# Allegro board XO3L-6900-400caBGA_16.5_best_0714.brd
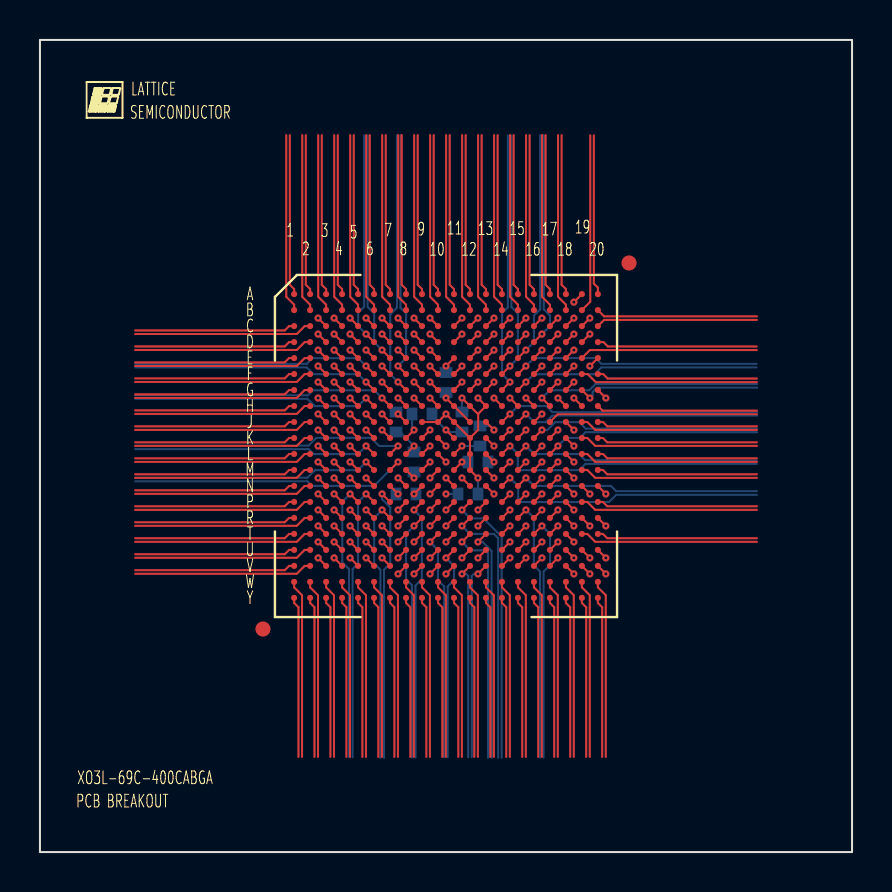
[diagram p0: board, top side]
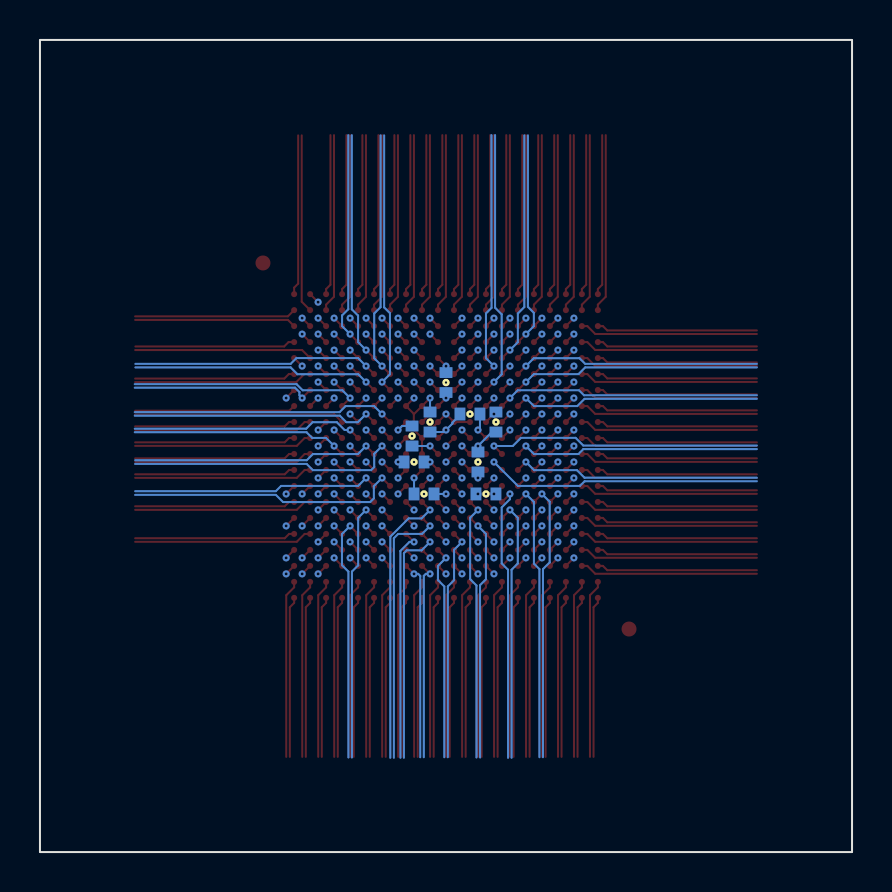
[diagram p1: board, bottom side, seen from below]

Outline 40.64 x 40.64 mm; copper layers: TOP, L2_GND, L3_SIGNAL, L4_SIGNAL, L5_PWR, BOTTOM. Coordinates in mm from the lower left corner of the outline.
Outline path: rectangle 0,0 40.64,40.64

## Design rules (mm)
net group CDPB4: nets PB4C PB4D
net group CDPB6: nets PB6C PB6D
net group CDPB7: nets PB7C PB7D
net group CDPB9: nets PB9C PB9D
net group CDPB10: nets PB10C PB10D
net group CDPB12: nets PB12C PB12D
net group CDPB13: nets PB13C PB13D
net group CDPB15: nets PB15C PB15D
net group CDPB16: nets PB16C PB16D
net group CDPB18: nets PB18C PB18D
net group CDPB21: nets PB21C PB21D
net group CDPB23: nets PB23C PB23D
net group CDPB26: nets PB26C PB26D
net group CDPB28: nets PB28C PB28D
net group CDPB29: nets PB29C PB29D
net group CDPB31: nets PB31C PB31D
net group CDPB32: nets PB32C PB32D
net group CDPB34: nets PB34C PB34D
net group CDPB35: nets PB35C PB35D
net group CDPB37: nets PB37C PB37D
net group CDPB38: nets PB38C PB38D
net group CDPL2: nets PL2C PL2D
net group CDPL3: nets PL3C PL3D
net group CDPL4: nets PL4C PL4D
net group CDPL5: nets PL5C PL5D
net group CDPL6: nets PL6C PL6D
net group CDPL7: nets PL7C PL7D
net group CDPL8: nets PL8C PL8D
net group CDPL9: nets PL9C PL9D
net group CDPL10: nets PL10C PL10D
net group CDPL11: nets PL11C PL11D
net group CDPL12: nets PL12C PL12D
net group CDPL14: nets PL14C PL14D
net group CDPL15: nets PL15C PL15D
net group CDPL16: nets PL16C PL16D
net group CDPL17: nets PL17C PL17D
net group CDPL18: nets PL18C PL18D
net group CDPL19: nets PL19C PL19D
net group CDPL20: nets PL20C PL20D
net group CDPL21: nets PL21C PL21D
net group CDPL22: nets PL22C PL22D
net group CDPL23: nets PL23C PL23D
net group CDPL24: nets PL24C PL24D
net group CDPL25: nets PL25C PL25D
net group CDPL26: nets PL26C PL26D
net group CDPL29: nets PL29C PL29D
net group CDPL32: nets PL32C PL32D
net group CDPL35: nets PL35C PL35D
net group CDPL38: nets PL38C PL38D
net group CDPL41: nets PL41C PL41D
net group CDPL44: nets PL44C PL44D
net group CDPL47: nets PL47C PL47D
net group CDPL50: nets PL50C PL50D
net group CDPL53: nets PL53C PL53D
net group CDPL56: nets PL56C PL56D
net group CDPL59: nets PL59C PL59D
net group CDPL62: nets PL62C PL62D
net group CDPL65: nets PL65C PL65D
net group CDPL68: nets PL68C PL68D
net group CDPL71: nets PL71C PL71D
net group CDPL74: nets PL74C PL74D
net group CDPL77: nets PL77C PL77D
net group CDPL80: nets PL80C PL80D
net group CDPL83: nets PL83C PL83D
net group CDPL86: nets PL86C PL86D
net group CDPL89: nets PL89C PL89D
net group CDPL92: nets PL92C PL92D
net group CDPR2: nets PR2C PR2D
net group CDPR3: nets PR3C PR3D
net group CDPR4: nets PR4C PR4D
net group CDPR5: nets PR5C PR5D
net group CDPR6: nets PR6C PR6D
net group CDPR7: nets PR7C PR7D
net group CDPR8: nets PR8C PR8D
net group CDPR9: nets PR9C PR9D
net group CDPR10: nets PR10C PR10D
net group CDPR11: nets PR11C PR11D
net group CDPR12: nets PR12C PR12D
net group CDPR14: nets PR14C PR14D
net group CDPR15: nets PR15C PR15D
net group CDPR16: nets PR16C PR16D
net group CDPR17: nets PR17C PR17D
net group CDPR18: nets PR18C PR18D
net group CDPR19: nets PR19C PR19D
net group CDPR20: nets PR20C PR20D
net group CDPR21: nets PR21C PR21D
net group CDPR22: nets PR22C PR22D
net group CDPR23: nets PR23C PR23D
net group CDPR24: nets PR24C PR24D
net group CDPR25: nets PR25C PR25D
net group CDPR26: nets PR26C PR26D
net group CDPR29: nets PR29C PR29D
net group CDPR32: nets PR32C PR32D
net group CDPR35: nets PR35C PR35D
net group CDPR38: nets PR38C PR38D
net group CDPR41: nets PR41C PR41D
net group CDPR44: nets PR44C PR44D
net group CDPR47: nets PR47C PR47D
net group CDPR50: nets PR50C PR50D
net group CDPR53: nets PR53C PR53D
net group CDPR56: nets PR56C PR56D
net group CDPR59: nets PR59C PR59D
net group CDPR62: nets PR62C PR62D
net group CDPR65: nets PR65C PR65D
net group CDPR68: nets PR68C PR68D
net group CDPR71: nets PR71C PR71D
net group CDPR74: nets PR74C PR74D
net group CDPR77: nets PR77C PR77D
net group CDPR80: nets PR80C PR80D
net group CDPR83: nets PR83C PR83D
net group CDPR86: nets PR86C PR86D
net group CDPR89: nets PR89C PR89D
net group CDPR92: nets PR92C PR92D
net group CDPT9: nets PT9C PT9D
net group CDPT10: nets PT10C PT10D
net group CDPT11: nets PT11C PT11D
net group CDPT12: nets PT12C PT12D
net group CDPT13: nets PT13C PT13D
net group CDPT14: nets PT14C PT14D
net group CDPT15: nets PT15C PT15D
net group CDPT16: nets PT16C PT16D
net group CDPT17: nets PT17C PT17D
net group CDPT18: nets PT18C PT18D
net group CDPT21: nets PT21C PT21D
net group CDPT22: nets PT22C PT22D
net group CDPT25: nets PT25C PT25D
net group CDPT26: nets PT26C PT26D
net group CDPT27: nets PT27C PT27D
net group CDPT28: nets PT28C PT28D
net group CDPT32: nets PT32C PT32D
net group CDPT33: nets PT33C PT33D
net group CDPT34: nets PT34C PT34D
net group CDPT35: nets PT35C PT35D
net group CDPT36: nets PT36C PT36D
net group PB4: nets PB4A PB4B
net group PB6: nets PB6A PB6B
net group PB7: nets PB7A PB7B
net group PB9: nets PB9A PB9B
net group PB10: nets PB10A PB10B
net group PB12: nets PB12A PB12B
net group PB13: nets PB13A PB13B
net group PB15: nets PB15A PB15B
net group PB16: nets PB16A PB16B
net group PB18: nets PB18A PB18B
net group PB21: nets PB21A PB21B
net group PB23: nets PB23A PB23B
net group PB26: nets PB26A PB26B
net group PB28: nets PB28A PB28B
net group PB29: nets PB29A PB29B
net group PB31: nets PB31A PB31B
net group PB32: nets PB32A PB32B
net group PB34: nets PB34A PB34B
net group PB35: nets PB35A PB35B
net group PB37: nets PB37A PB37B
net group PB38: nets PB38A PB38B
net group PB98: nets PB98A PB98B
net group PL2: nets PL2A PL2B
net group PL3: nets PL3A PL3B
net group PL4: nets PL4A PL4B
net group PL5: nets PL5A PL5B
net group PL6: nets PL6A PL6B
net group PL7: nets PL7A PL7B
net group PL8: nets PL8A PL8B
net group PL9: nets PL9A PL9B
net group PL10: nets PL10A PL10B
net group PL11: nets PL11A PL11B
net group PL12: nets PL12A PL12B
net group PL14: nets PL14A PL14B
net group PL15: nets PL15A PL15B
net group PL16: nets PL16A PL16B
net group PL17: nets PL17A PL17B
net group PL18: nets PL18A PL18B
net group PL19: nets PL19A PL19B
net group PL20: nets PL20A PL20B
net group PL21: nets PL21A PL21B
net group PL22: nets PL22A PL22B
net group PL23: nets PL23A PL23B
net group PL24: nets PL24A PL24B
net group PL25: nets PL25A PL25B
net group PL29: nets PL29A PL29B
net group PL32: nets PL32A PL32B
net group PL35: nets PL35A PL35B
net group PL38: nets PL38A PL38B
net group PL41: nets PL41A PL41B
net group PL44: nets PL44A PL44B
net group PL47: nets PL47A PL47B
net group PL50: nets PL50A PL50B
net group PL53: nets PL53A PL53B
net group PL56: nets PL56A PL56B
net group PL59: nets PL59A PL59B
net group PL62: nets PL62A PL62B
net group PL65: nets PL65A PL65B
net group PL68: nets PL68A PL68B
net group PL71: nets PL71A PL71B
net group PL74: nets PL74A PL74B
net group PL77: nets PL77A PL77B
net group PL80: nets PL80A PL80B
net group PL83: nets PL83A PL83B
net group PL86: nets PL86A PL86B
net group PL89: nets PL89A PL89B
net group PL92: nets PL92A PL92B
net group PR2: nets PR2A PR2B
net group PR3: nets PR3A PR3B
net group PR4: nets PR4A PR4B
net group PR5: nets PR5A PR5B
net group PR6: nets PR6A PR6B
net group PR7: nets PR7A PR7B
net group PR8: nets PR8A PR8B
net group PR9: nets PR9A PR9B
net group PR10: nets PR10A PR10B
net group PR11: nets PR11A PR11B
net group PR12: nets PR12A PR12B
net group PR14: nets PR14A PR14B
net group PR15: nets PR15A PR15B
net group PR16: nets PR16A PR16B
net group PR17: nets PR17A PR17B
net group PR18: nets PR18A PR18B
net group PR19: nets PR19A PR19B
net group PR20: nets PR20A PR20B
net group PR21: nets PR21A PR21B
net group PR22: nets PR22A PR22B
net group PR23: nets PR23A PR23B
net group PR24: nets PR24A PR24B
net group PR25: nets PR25A PR25B
net group PR26: nets PR26A PR26B
net group PR29: nets PR29A PR29B
net group PR32: nets PR32A PR32B
net group PR35: nets PR35A PR35B
net group PR38: nets PR38A PR38B
net group PR41: nets PR41A PR41B
net group PR44: nets PR44A PR44B
net group PR47: nets PR47A PR47B
net group PR50: nets PR50A PR50B
net group PR53: nets PR53A PR53B
net group PR56: nets PR56A PR56B
net group PR59: nets PR59A PR59B
net group PR62: nets PR62A PR62B
net group PR65: nets PR65A PR65B
net group PR68: nets PR68A PR68B
net group PR71: nets PR71A PR71B
net group PR74: nets PR74A PR74B
net group PR77: nets PR77A PR77B
net group PR80: nets PR80A PR80B
net group PR83: nets PR83A PR83B
net group PR86: nets PR86A PR86B
net group PR89: nets PR89A PR89B
net group PR92: nets PR92A PR92B
net group PT4: nets PT4A PT4B
net group PT6: nets PT6A PT6B
net group PT9: nets PT9A PT9B
net group PT10: nets PT10A PT10B
net group PT11: nets PT11A PT11B
net group PT12: nets PT12A PT12B
net group PT13: nets PT13A PT13B
net group PT14: nets PT14A PT14B
net group PT15: nets PT15A PT15B
net group PT16: nets PT16A PT16B
net group PT17: nets PT17A PT17B
net group PT18: nets PT18A PT18B
net group PT20: nets PT20A PT20B
net group PT21: nets PT21A PT21B
net group PT22: nets PT22A PT22B
net group PT24: nets PT24A PT24B
net group PT25: nets PT25A PT25B
net group PT26: nets PT26A PT26B
net group PT27: nets PT27A PT27B
net group PT28: nets PT28A PT28B
net group PT29: nets PT29A PT29B
net group PT31: nets PT31A PT31B
net group PT32: nets PT32A PT32B
net group PT33: nets PT33A PT33B
net group PT34: nets PT34A PT34B
net group PT35: nets PT35A PT35B
net group PT36: nets PT36A PT36B
net group PT38: nets PT38A PT38B
net group PT40: nets PT40A PT40B
net group PT42: nets PT42A PT42B
net group PT44: nets PT44A PT44B
net group PT45: nets PT45A PT45B
net group PT47: nets PT47A PT47B
net group PT49: nets PT49A PT49B
net group PT51: nets PT51A PT51B
net group PT54: nets PT54A PT54B
net group PT56: nets PT56A PT56B
net group PT58: nets PT58A PT58B
net group PT60: nets PT60A PT60B
net group PT63: nets PT63A PT63B
net group PT65: nets PT65A PT65B
net group PT69: nets PT69A PT69B
net group PT71: nets PT71A PT71B
net group PT74: nets PT74A PT74B
net group PT76: nets PT76A PT76B
net group PT101: nets PT101A PT101B
net group PT103: nets PT103A PT103B
net group PT105: nets PT105A PT105B
net group PT107: nets PT107A PT107B
net group PT110: nets PT110A PT110B
net group PT112: nets PT112A PT112B
net group PT114: nets PT114A PT114B
net group PT116: nets PT116A PT116B
net group PT119: nets PT119A PT119B
net group PT121: nets PT121A PT121B

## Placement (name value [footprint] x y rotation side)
BGA  -  [BGA400C80P20X20_1700X1700X13-1]  20.32 20.32 270 top
C1  VAL  [C0402]  20.32 23.5 270 bottom
C2  VAL  [C0402]  18.32 17.92 0 bottom
C3  VAL  [C0402]  17.82 21.52 90 bottom
C4  VAL  [C0402]  21.12 21.52 270 bottom
C5  VAL  [C0402]  21.92 19.52 180 bottom
C6  VAL  [C0402]  22.02 20.82 90 bottom
C7  VAL  [C0402]  21.42 17.92 180 bottom
C11  VAL  [C0402]  18.72 19.52 90 bottom
C12  VAL  [C0402]  19.12 21.92 180 bottom
NOREF  -  []  24.69 13 0 top

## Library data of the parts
BGA = BGA400C80P20X20_1700X1700X13-1
C1 C4-C7 C11 C12 = C0402: Tolerance: TOL; User Part Number: UPN
C2 C3 = C0402: User Part Number: UPN; Tolerance: TOL

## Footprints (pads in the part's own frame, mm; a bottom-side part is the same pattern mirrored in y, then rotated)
BGA400C80P20X20_1700X1700X13-1
  round 0.75 smd: (-9.16,9.16) (9.16,-9.16)
  round 0.305 smd: A1(-7.6,-7.6) A2(-7.6,-6.8) A3(-7.6,-6) A4(-7.6,-5.2) A5(-7.6,-4.4) A6(-7.6,-3.6) A7(-7.6,-2.8) A8(-7.6,-2) A9(-7.6,-1.2) A10(-7.6,-0.4) A11(-7.6,0.4) A12(-7.6,1.2) A13(-7.6,2) A14(-7.6,2.8) A15(-7.6,3.6) A16(-7.6,4.4) A17(-7.6,5.2) A18(-7.6,6) A19(-7.6,6.8) A20(-7.6,7.6) B1(-6.8,-7.6) B2(-6.8,-6.8) B3(-6.8,-6) B4(-6.8,-5.2) B5(-6.8,-4.4) B6(-6.8,-3.6) B7(-6.8,-2.8) B8(-6.8,-2) B9(-6.8,-1.2) B10(-6.8,-0.4) B11(-6.8,0.4) B12(-6.8,1.2) B13(-6.8,2) B14(-6.8,2.8) B15(-6.8,3.6) B16(-6.8,4.4) B17(-6.8,5.2) B18(-6.8,6) B19(-6.8,6.8) B20(-6.8,7.6) C1(-6,-7.6) C2(-6,-6.8) C3(-6,-6) C4(-6,-5.2) C5(-6,-4.4) C6(-6,-3.6) C7(-6,-2.8) C8(-6,-2) C9(-6,-1.2) C10(-6,-0.4) C11(-6,0.4) C12(-6,1.2) C13(-6,2) C14(-6,2.8) C15(-6,3.6) C16(-6,4.4) C17(-6,5.2) C18(-6,6) C19(-6,6.8) C20(-6,7.6) D1(-5.2,-7.6) D2(-5.2,-6.8) D3(-5.2,-6) D4(-5.2,-5.2) D5(-5.2,-4.4) D6(-5.2,-3.6) D7(-5.2,-2.8) D8(-5.2,-2) D9(-5.2,-1.2) D10(-5.2,-0.4) D11(-5.2,0.4) D12(-5.2,1.2) D13(-5.2,2) D14(-5.2,2.8) D15(-5.2,3.6) D16(-5.2,4.4) D17(-5.2,5.2) D18(-5.2,6) D19(-5.2,6.8) D20(-5.2,7.6) E1(-4.4,-7.6) E2(-4.4,-6.8) E3(-4.4,-6) E4(-4.4,-5.2) E5(-4.4,-4.4) E6(-4.4,-3.6) E7(-4.4,-2.8) E8(-4.4,-2) E9(-4.4,-1.2) E10(-4.4,-0.4) E11(-4.4,0.4) E12(-4.4,1.2) E13(-4.4,2) E14(-4.4,2.8) E15(-4.4,3.6) E16(-4.4,4.4) E17(-4.4,5.2) E18(-4.4,6) E19(-4.4,6.8) E20(-4.4,7.6) F1(-3.6,-7.6) F2(-3.6,-6.8) F3(-3.6,-6) F4(-3.6,-5.2) F5(-3.6,-4.4) F6(-3.6,-3.6) F7(-3.6,-2.8) F8(-3.6,-2) F9(-3.6,-1.2) F10(-3.6,-0.4) F11(-3.6,0.4) F12(-3.6,1.2) F13(-3.6,2) F14(-3.6,2.8) F15(-3.6,3.6) F16(-3.6,4.4) F17(-3.6,5.2) F18(-3.6,6) F19(-3.6,6.8) F20(-3.6,7.6) G1(-2.8,-7.6) G2(-2.8,-6.8) G3(-2.8,-6) G4(-2.8,-5.2) G5(-2.8,-4.4) G6(-2.8,-3.6) G7(-2.8,-2.8) G8(-2.8,-2) G9(-2.8,-1.2) G10(-2.8,-0.4) G11(-2.8,0.4) G12(-2.8,1.2) G13(-2.8,2) G14(-2.8,2.8) G15(-2.8,3.6) G16(-2.8,4.4) G17(-2.8,5.2) G18(-2.8,6) G19(-2.8,6.8) G20(-2.8,7.6) H1(-2,-7.6) H2(-2,-6.8) H3(-2,-6) H4(-2,-5.2) H5(-2,-4.4) H6(-2,-3.6) H7(-2,-2.8) H8(-2,-2) H9(-2,-1.2) H10(-2,-0.4) H11(-2,0.4) H12(-2,1.2) H13(-2,2) H14(-2,2.8) H15(-2,3.6) H16(-2,4.4) H17(-2,5.2) H18(-2,6) H19(-2,6.8) H20(-2,7.6) J1(-1.2,-7.6) J2(-1.2,-6.8) J3(-1.2,-6) J4(-1.2,-5.2) J5(-1.2,-4.4) J6(-1.2,-3.6) J7(-1.2,-2.8) J8(-1.2,-2) J9(-1.2,-1.2) J10(-1.2,-0.4) J11(-1.2,0.4) J12(-1.2,1.2) J13(-1.2,2) J14(-1.2,2.8) J15(-1.2,3.6) J16(-1.2,4.4) J17(-1.2,5.2) J18(-1.2,6) J19(-1.2,6.8) J20(-1.2,7.6) K1(-0.4,-7.6) K2(-0.4,-6.8) K3(-0.4,-6) K4(-0.4,-5.2) K5(-0.4,-4.4) K6(-0.4,-3.6) K7(-0.4,-2.8) K8(-0.4,-2) K9(-0.4,-1.2) K10(-0.4,-0.4) K11(-0.4,0.4) K12(-0.4,1.2) K13(-0.4,2) K14(-0.4,2.8) K15(-0.4,3.6) K16(-0.4,4.4) K17(-0.4,5.2) K18(-0.4,6) K19(-0.4,6.8) K20(-0.4,7.6) L1(0.4,-7.6) L2(0.4,-6.8) L3(0.4,-6) L4(0.4,-5.2) L5(0.4,-4.4) L6(0.4,-3.6) L7(0.4,-2.8) L8(0.4,-2) L9(0.4,-1.2) L10(0.4,-0.4) L11(0.4,0.4) L12(0.4,1.2) L13(0.4,2) L14(0.4,2.8) L15(0.4,3.6) L16(0.4,4.4) L17(0.4,5.2) L18(0.4,6) L19(0.4,6.8) L20(0.4,7.6) M1(1.2,-7.6) M2(1.2,-6.8) M3(1.2,-6) M4(1.2,-5.2) M5(1.2,-4.4) M6(1.2,-3.6) M7(1.2,-2.8) M8(1.2,-2) M9(1.2,-1.2) M10(1.2,-0.4) M11(1.2,0.4) M12(1.2,1.2) M13(1.2,2) M14(1.2,2.8) M15(1.2,3.6) M16(1.2,4.4) M17(1.2,5.2) M18(1.2,6) M19(1.2,6.8) M20(1.2,7.6) N1(2,-7.6) N2(2,-6.8) N3(2,-6) N4(2,-5.2) N5(2,-4.4) N6(2,-3.6) N7(2,-2.8) N8(2,-2) N9(2,-1.2) N10(2,-0.4) N11(2,0.4) N12(2,1.2) N13(2,2) N14(2,2.8) N15(2,3.6) N16(2,4.4) N17(2,5.2) N18(2,6) N19(2,6.8) N20(2,7.6) P1(2.8,-7.6) P2(2.8,-6.8) P3(2.8,-6) P4(2.8,-5.2) P5(2.8,-4.4) P6(2.8,-3.6) P7(2.8,-2.8) P8(2.8,-2) P9(2.8,-1.2) P10(2.8,-0.4) P11(2.8,0.4) P12(2.8,1.2) P13(2.8,2) P14(2.8,2.8) P15(2.8,3.6) P16(2.8,4.4) P17(2.8,5.2) P18(2.8,6) P19(2.8,6.8) P20(2.8,7.6) R1(3.6,-7.6) R2(3.6,-6.8) R3(3.6,-6) R4(3.6,-5.2) R5(3.6,-4.4) R6(3.6,-3.6) R7(3.6,-2.8) R8(3.6,-2) R9(3.6,-1.2) R10(3.6,-0.4) R11(3.6,0.4) R12(3.6,1.2) R13(3.6,2) R14(3.6,2.8) R15(3.6,3.6) R16(3.6,4.4) R17(3.6,5.2) R18(3.6,6) R19(3.6,6.8) R20(3.6,7.6) T1(4.4,-7.6) T2(4.4,-6.8) T3(4.4,-6) T4(4.4,-5.2) T5(4.4,-4.4) T6(4.4,-3.6) T7(4.4,-2.8) T8(4.4,-2) T9(4.4,-1.2) T10(4.4,-0.4) T11(4.4,0.4) T12(4.4,1.2) T13(4.4,2) T14(4.4,2.8) T15(4.4,3.6) T16(4.4,4.4) T17(4.4,5.2) T18(4.4,6) T19(4.4,6.8) T20(4.4,7.6) U1(5.2,-7.6) U2(5.2,-6.8) U3(5.2,-6) U4(5.2,-5.2) U5(5.2,-4.4) U6(5.2,-3.6) U7(5.2,-2.8) U8(5.2,-2) U9(5.2,-1.2) U10(5.2,-0.4) U11(5.2,0.4) U12(5.2,1.2) U13(5.2,2) U14(5.2,2.8) U15(5.2,3.6) U16(5.2,4.4) U17(5.2,5.2) U18(5.2,6) U19(5.2,6.8) U20(5.2,7.6) V1(6,-7.6) V2(6,-6.8) V3(6,-6) V4(6,-5.2) V5(6,-4.4) V6(6,-3.6) V7(6,-2.8) V8(6,-2) V9(6,-1.2) V10(6,-0.4) V11(6,0.4) V12(6,1.2) V13(6,2) V14(6,2.8) V15(6,3.6) V16(6,4.4) V17(6,5.2) V18(6,6) V19(6,6.8) V20(6,7.6) W1(6.8,-7.6) W2(6.8,-6.8) W3(6.8,-6) W4(6.8,-5.2) W5(6.8,-4.4) W6(6.8,-3.6) W7(6.8,-2.8) W8(6.8,-2) W9(6.8,-1.2) W10(6.8,-0.4) W11(6.8,0.4) W12(6.8,1.2) W13(6.8,2) W14(6.8,2.8) W15(6.8,3.6) W16(6.8,4.4) W17(6.8,5.2) W18(6.8,6) W19(6.8,6.8) W20(6.8,7.6) Y1(7.6,-7.6) Y2(7.6,-6.8) Y3(7.6,-6) Y4(7.6,-5.2) Y5(7.6,-4.4) Y6(7.6,-3.6) Y7(7.6,-2.8) Y8(7.6,-2) Y9(7.6,-1.2) Y10(7.6,-0.4) Y11(7.6,0.4) Y12(7.6,1.2) Y13(7.6,2) Y14(7.6,2.8) Y15(7.6,3.6) Y16(7.6,4.4) Y17(7.6,5.2) Y18(7.6,6) Y19(7.6,6.8) Y20(7.6,7.6)
C0402
  rect 0.54x0.64 smd: 1(-0.5,0) 2(0.5,0)

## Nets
GND: BGA.C5 BGA.D3 BGA.D4 BGA.E5 BGA.E9 BGA.E10 BGA.E11 BGA.E12 BGA.E13 BGA.E16 BGA.E18 BGA.G18 BGA.H5 BGA.K3 BGA.K10 BGA.K11 BGA.L8 BGA.L10 BGA.L11 BGA.L18 BGA.M11 BGA.N7 BGA.R18 BGA.T15 BGA.U3 BGA.U7 BGA.U8 BGA.U13 BGA.U16 BGA.V5 BGA.V7 BGA.V11 BGA.V18 C1.1 C2.1 C3.1 C4.2 C5.2 C6.1 C7.2 C11.2 C12.1
VCC: BGA.H12 BGA.H13 BGA.J9 BGA.J10 BGA.J11 BGA.K12 BGA.L9 BGA.L12 BGA.M10 BGA.M12 C4.1 C7.1
VCCIO0: BGA.H8 BGA.H9 BGA.H10 BGA.H11 BGA.J12 C1.2
VCCIO1: BGA.J13 BGA.K13 BGA.L13 BGA.M13 BGA.N13 C5.1 C6.2
VCCIO2: BGA.N8 BGA.N9 BGA.N10 BGA.N11 BGA.N12 C2.2
VCCIO3: BGA.M8 BGA.M9 C11.1
VCCIO4: BGA.K8 BGA.K9 C12.2
VCCIO5: BGA.J7 BGA.J8 C3.2
PB4A: BGA.W1
PB4B: BGA.Y1
PB4C: BGA.R6
PB4D: BGA.T6
PB6A: BGA.W2
PB6B: BGA.Y2
PB6C: BGA.P7
PB6D: BGA.R7
PB7A: BGA.W3
PB7B: BGA.Y3
PB7C: BGA.V6
PB7D: BGA.U6
PB9A: BGA.W4
PB9B: BGA.Y4
PB9C: BGA.P8
PB9D: BGA.R8
PB10A: BGA.W5
PB10B: BGA.Y5
PB10C: BGA.T7
PB10D: BGA.T8
PB12A: BGA.W6
PB12B: BGA.Y6
PB12C: BGA.P9
PB12D: BGA.R9
PB13A: BGA.W7
PB13B: BGA.Y7
PB13C: BGA.V8
PB13D: BGA.U9
PB15A: BGA.W8
PB15B: BGA.Y8
PB15C: BGA.V9
PB15D: BGA.T9
PB16A: BGA.W9
PB16B: BGA.Y9
PB16C: BGA.P10
PB16D: BGA.R10
PB18A: BGA.Y10
PB18B: BGA.W10
PB18C: BGA.U10
PB18D: BGA.V10
PB21A: BGA.Y11
PB21B: BGA.W11
PB21C: BGA.U11
PB21D: BGA.T10
PB23A: BGA.Y12
PB23B: BGA.W12
PB23C: BGA.P11
PB23D: BGA.R11
PB26A: BGA.Y13
PB26B: BGA.W13
PB26C: BGA.V12
PB26D: BGA.V13
PB28A: BGA.Y14
PB28B: BGA.W14
PB28C: BGA.U12
PB28D: BGA.T11
PB29A: BGA.Y15
PB29B: BGA.W15
PB29C: BGA.P12
PB29D: BGA.R12
PB31A: BGA.Y16
PB31B: BGA.W16
PB31C: BGA.T12
PB31D: BGA.T13
PB32A: BGA.Y17
PB32B: BGA.W17
PB32C: BGA.P13
PB32D: BGA.R13
PB34A: BGA.V14
PB34B: BGA.U14
PB34C: BGA.V15
PB34D: BGA.V16
PB35A: BGA.Y18
PB35B: BGA.W18
PB35C: BGA.T14
PB35D: BGA.U15
PB37A: BGA.Y19
PB37B: BGA.W19
PB37C: BGA.P14
PB37D: BGA.R14
PB38A: BGA.Y20
PB38B: BGA.W20
PB38C: BGA.T16
PB38D: BGA.R15
PL2A: BGA.C4
PL2B: BGA.C3
PL2C: BGA.F6
PL2D: BGA.G6
PL3A: BGA.C2
PL3B: BGA.C1
PL3C: BGA.E4
PL3D: BGA.E3
PL4A: BGA.D2
PL4B: BGA.D1
PL4C: BGA.F5
PL4D: BGA.G5
PL5A: BGA.F4
PL5B: BGA.F3
PL5C: BGA.H6
PL5D: BGA.H7
PL6A: BGA.E2
PL6B: BGA.E1
PL6C: BGA.F2
PL6D: BGA.F1
PL7A: BGA.G4
PL7B: BGA.G3
PL7C: BGA.H3
PL7D: BGA.H4
PL8A: BGA.G2
PL8B: BGA.G1
PL8C: BGA.J6
PL8D: BGA.J5
PL9A: BGA.H2
PL9B: BGA.H1
PL9C: BGA.J4
PL9D: BGA.J3
PL10A: BGA.J2
PL10B: BGA.J1
PL10C: BGA.K5
PL10D: BGA.K4
PL11A: BGA.K2
PL11B: BGA.K1
PL11C: BGA.K6
PL11D: BGA.K7
PL12A: BGA.L1
PL12B: BGA.L2
PL12C: BGA.L3
PL12D: BGA.L4
PL15A: BGA.M1
PL15B: BGA.M2
PL15C: BGA.M3
PL15D: BGA.M4
PL16A: BGA.L5
PL16B: BGA.M5
PL16C: BGA.L6
PL16D: BGA.L7
PL17A: BGA.N1
PL17B: BGA.N2
PL17C: BGA.P1
PL17D: BGA.P2
PL18A: BGA.N3
PL18B: BGA.N4
PL18C: BGA.M6
PL18D: BGA.M7
PL19A: BGA.P3
PL19B: BGA.P4
PL19C: BGA.R1
PL19D: BGA.R2
PL21A: BGA.T1
PL21B: BGA.T2
PL21C: BGA.N5
PL21D: BGA.N6
PL22A: BGA.U1
PL22B: BGA.U2
PL22C: BGA.R3
PL22D: BGA.R4
PL23A: BGA.T3
PL23B: BGA.T4
PL23C: BGA.V1
PL23D: BGA.V2
PL24A: BGA.V3
PL24B: BGA.V4
PL24C: BGA.P5
PL24D: BGA.P6
PL25A: BGA.T5
PL25B: BGA.R5
PL25C: BGA.U4
PL25D: BGA.U5
PR2A: BGA.D17
PR2B: BGA.C18
PR2C: BGA.F15
PR2D: BGA.G15
PR3A: BGA.C19
PR3B: BGA.E17
PR3C: BGA.F16
PR3D: BGA.D18
PR4A: BGA.B20
PR4B: BGA.C20
PR4C: BGA.H14
PR4D: BGA.H15
PR5A: BGA.D19
PR5B: BGA.F17
PR5C: BGA.D20
PR5D: BGA.E19
PR6A: BGA.G16
PR6B: BGA.F18
PR6C: BGA.G17
PR6D: BGA.E20
PR7A: BGA.F19
PR7B: BGA.F20
PR7C: BGA.J14
PR7D: BGA.J15
PR8A: BGA.G19
PR8B: BGA.H17
PR8C: BGA.H16
PR8D: BGA.G20
PR9A: BGA.H18
PR9B: BGA.H19
PR9C: BGA.J17
PR9D: BGA.H20
PR10A: BGA.J18
PR10B: BGA.J16
PR10C: BGA.K14
PR10D: BGA.K15
PR11A: BGA.J19
PR11B: BGA.J20
PR11C: BGA.K17
PR11D: BGA.K18
PR12A: BGA.K19
PR12B: BGA.K20
PR12C: BGA.K16
PR12D: BGA.L17
PR15A: BGA.L19
PR15B: BGA.L20
PR15C: BGA.L14
PR15D: BGA.L15
PR16A: BGA.M20
PR16B: BGA.M19
PR16C: BGA.L16
PR16D: BGA.M18
PR17A: BGA.M17
PR17B: BGA.N20
PR17C: BGA.M16
PR17D: BGA.N19
PR18A: BGA.N18
PR18B: BGA.N17
PR18C: BGA.P20
PR18D: BGA.P19
PR19A: BGA.P18
PR19B: BGA.R20
PR19C: BGA.M15
PR19D: BGA.M14
PR21A: BGA.N16
PR21B: BGA.R19
PR21C: BGA.T20
PR21D: BGA.T19
PR22A: BGA.U20
PR22B: BGA.P17
PR22C: BGA.T18
PR22D: BGA.U19
PR23A: BGA.V20
PR23B: BGA.P16
PR23C: BGA.N15
PR23D: BGA.N14
PR24A: BGA.R17
PR24B: BGA.U18
PR24C: BGA.P15
PR24D: BGA.R16
PR25A: BGA.V19
PR25B: BGA.T17
PR25C: BGA.U17
PR25D: BGA.V17
PT9A: BGA.B1
PT9B: BGA.A1
PT9C: BGA.G7
PT9D: BGA.F7
PT10A: BGA.B2
PT10B: BGA.A2
PT10C: BGA.E6
PT10D: BGA.D5
PT11A: BGA.B3
PT11B: BGA.A3
PT11C: BGA.D6
PT11D: BGA.E7
PT12A: BGA.B4
PT12B: BGA.A4
PT12C: BGA.C6
PT12D: BGA.D7
PT13A: BGA.B5
PT13B: BGA.A5
PT13C: BGA.G8
PT13D: BGA.F8
PT14A: BGA.B6
PT14B: BGA.A6
PT14C: BGA.E8
PT14D: BGA.C7
PT15A: BGA.B7
PT15B: BGA.A7
PT15C: BGA.G9
PT15D: BGA.F9
PT16A: BGA.B8
PT16B: BGA.A8
PT16C: BGA.D8
PT16D: BGA.C8
PT17A: BGA.B9
PT17B: BGA.A9
PT17C: BGA.C9
PT17D: BGA.D9
PT18A: BGA.B10
PT18B: BGA.A10
PT18C: BGA.G10
PT18D: BGA.F10
PT21A: BGA.B11
PT21B: BGA.A11
PT21C: BGA.D10
PT21D: BGA.C10
PT22A: BGA.A12
PT22B: BGA.B12
PT22C: BGA.C11
PT22D: BGA.D11
PT25A: BGA.A13
PT25B: BGA.B13
PT25C: BGA.G11
PT25D: BGA.F11
PT26A: BGA.A14
PT26B: BGA.B14
PT26C: BGA.D12
PT26D: BGA.C12
PT27A: BGA.A15
PT27B: BGA.B15
PT27C: BGA.C13
PT27D: BGA.D13
PT28A: BGA.A16
PT28B: BGA.B16
PT28C: BGA.G12
PT28D: BGA.F12
PT32A: BGA.A17
PT32B: BGA.B17
PT32C: BGA.C14
PT32D: BGA.D14
PT33A: BGA.C15
PT33B: BGA.C16
PT33C: BGA.G13
PT33D: BGA.F13
PT34A: BGA.A18
PT34B: BGA.B18
PT34C: BGA.E14
PT34D: BGA.D15
PT35A: BGA.E15
PT35B: BGA.D16
PT35C: BGA.G14
PT35D: BGA.F14
PT36A: BGA.B19
PT36B: BGA.A20
PT36C: BGA.C17
PT36D: BGA.A19

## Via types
v1: diameter 0.356, hole 0.152, TOP to BOTTOM, 266 vias

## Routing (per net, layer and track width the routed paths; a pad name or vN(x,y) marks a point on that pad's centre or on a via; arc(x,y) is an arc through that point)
GND: length 24.2
  TOP w0.102: BGA.E9 v1(18.72,25.12) ; BGA.V7 v1(17.12,14.72) ; BGA.U3 v1(13.92,15.52) ; BGA.L11 v1(21.12,20.32) ; BGA.U16 v1(25.12,15.52) ; BGA.E10 v1(19.52,25.12) ; BGA.M11 v1(21.12,19.52) ; BGA.K3 v1(13.92,21.12) ; BGA.L10 v1(20.32,19.52) ; BGA.G18 v1(26.72,23.52) ; BGA.R18 v1(26.72,16.32) ; BGA.K11 v1(20.32,21.12) ; BGA.L8 v1(18.72,20.32) ; BGA.K10 v1(20.32,20.32) ; BGA.D4 v1(14.72,25.92) ; BGA.E12 v1(21.92,25.12) ; BGA.V5 v1(15.52,14.72) ; BGA.U7 v1(17.12,15.52) ; BGA.V18 v1(26.72,13.92) ; BGA.T15 v1(24.32,16.32) ; BGA.N7 v1(17.92,17.92) ; BGA.E18 v1(26.72,25.12) ; BGA.E16 v1(25.12,25.12) ; BGA.V11 v1(20.32,13.92) ; BGA.E5 v1(15.52,25.12) ; BGA.E13 v1(22.72,25.12) ; BGA.C5 v1(15.52,26.72) ; BGA.L18 v1(26.72,19.52) ; BGA.U8 v1(17.92,14.72) ; BGA.D3 v1(13.92,25.92) ; BGA.U13 v1(21.92,14.72) ; BGA.H5 v1(15.52,22.72) ; BGA.E11 v1(20.32,24.32)
  BOTTOM w0.102: C1.1 v1(20.32,24.32) ; C12.1 19.62,21.87 20,21.49 20,21.44 v1(20.32,21.12) 20.42,21.02 C4.2 ; C5.2 v1(21.12,19.52) ; C11.2 v1(18.72,20.32) 18.02,21.02 C3.1 ; C7.2 v1(20.32,17.92) ; C6.1 v1(21.12,20.32)
VCC: length 11.5
  TOP w0.102: BGA.K12 21.93,21.13 21.93,21.91 ; BGA.K12 BGA.L12 BGA.M12 v1(21.92,18.72) ; BGA.K12 BGA.J11 v1(20.32,21.92) BGA.J10 BGA.J9 ; BGA.M10 v1(19.52,18.72) ; v1(21.12,22.72) BGA.H12 21.93,21.91 ; 21.93,21.91 21.93,21.93 BGA.H13 v1(21.92,22.72) ; BGA.L9 v1(19.52,20.32)
  BOTTOM w0.102: C4.1 v1(21.12,22.72) ; C7.1 v1(21.92,18.72)
VCCIO0: length 3.7
  TOP w0.102: BGA.J12 BGA.H11 v1(20.32,22.72) ; BGA.H9 v1(18.72,22.72) ; BGA.H10 v1(19.52,22.72) ; BGA.H8 v1(17.92,22.72)
  BOTTOM w0.102: C1.2 v1(20.32,22.72)
VCCIO1: length 3.9
  TOP w0.102: BGA.J13 v1(22.72,21.12) ; BGA.K13 v1(22.72,20.32) ; BGA.N13 v1(22.72,17.92) ; BGA.L13 v1(22.72,19.52) ; BGA.M13 v1(22.72,18.72)
  BOTTOM w0.102: C5.1 v1(22.72,19.52) ; v1(22.72,21.12) 22.52,21.32 C6.2
VCCIO2: length 2.8
  TOP w0.102: BGA.N12 v1(21.12,18.72) ; BGA.N11 v1(20.32,18.72) ; BGA.N10 v1(19.52,17.92) ; BGA.N9 v1(18.72,17.92) ; BGA.N8 v1(17.92,18.72)
VCCIO3: length 1.4
  TOP w0.102: BGA.M8 v1(18.72,18.72) ; BGA.M9 v1(19.52,19.52)
  BOTTOM w0.102: C11.1 v1(18.72,18.72)
VCCIO4: length 2
  TOP w0.102: BGA.K8 v1(18.72,21.12) ; BGA.K9 v1(19.52,21.12)
  BOTTOM w0.102: v1(18.72,21.12) 18.62,21.22 C12.2
VCCIO5: length 1.1
  TOP w0.102: BGA.J8 v1(17.92,21.92) ; BGA.J7 v1(17.12,21.92)
PB4A: length 8.9
  TOP w0.102: 13.11,4.76 13.11,12.85 12.72,13.25 BGA.W1
PB4B: length 8
  TOP w0.102: 12.94,4.76 12.94,12.25 12.72,12.47 BGA.Y1
PB4C: length 13.2
  TOP w0.102: BGA.R6 v1(16.32,17.12)
  L4_SIGNAL w0.102: v1(16.32,17.12) 15.92,16.72 15.92,14.48 16.22,14.18 16.22,4.76
PB4D: length 12.4
  TOP w0.102: BGA.T6 v1(16.32,16.32)
  L4_SIGNAL w0.102: 16.39,4.76 16.39,14.18 16.73,14.51 16.73,15.91 v1(16.32,16.32)
PB6A: length 8.9
  TOP w0.102: BGA.W2 13.52,13.25 13.91,12.85 13.91,4.76
PB6B: length 8
  TOP w0.102: BGA.Y2 13.52,12.47 13.74,12.25 13.74,4.76
PB6C: length 14.1
  TOP w0.102: BGA.P7 v1(17.12,17.92)
  BOTTOM w0.102: v1(17.12,17.92) 17.12,17.66 17.53,17.25 17.53,14.44 17.22,14.13 17.22,4.72
PB6D: length 13.3
  TOP w0.102: BGA.R7 v1(17.12,17.12)
  BOTTOM w0.102: 17.04,4.72 17.04,14.13 16.73,14.44 16.73,16.73 v1(17.12,17.12)
PB7A: length 8.9
  TOP w0.102: BGA.W3 14.32,13.25 14.71,12.85 14.71,4.76
PB7B: length 8
  TOP w0.102: 14.54,4.76 14.54,12.25 14.32,12.47 BGA.Y3
PB7C: length 10.6
  TOP w0.102: BGA.V6 v1(16.32,14.72)
  L3_SIGNAL w0.102: 16.1,4.75 16.1,14.13 16.32,14.35 v1(16.32,14.72)
PB7D: length 11.5
  TOP w0.102: BGA.U6 v1(16.32,15.52)
  L3_SIGNAL w0.102: 15.92,4.75 15.92,15.12 v1(16.32,15.52)
PB9A: length 8.9
  TOP w0.102: BGA.W4 15.12,13.25 15.51,12.85 15.51,4.76
PB9B: length 8
  TOP w0.102: 15.34,4.76 15.34,12.25 15.12,12.47 BGA.Y4
PB9C: length 13.2
  TOP w0.102: BGA.P8 v1(17.92,17.12)
  L4_SIGNAL w0.102: 17.82,4.76 17.82,13.42 17.52,13.71 17.52,16.72 v1(17.92,17.12)
PB9D: length 12.4
  TOP w0.102: BGA.R8 v1(17.92,16.32)
  L4_SIGNAL w0.102: v1(17.92,16.32) 18.32,15.92 18.32,13.75 17.99,13.42 17.99,4.76
PB10A: length 8.9
  TOP w0.102: 16.31,4.76 16.31,12.85 15.92,13.25 BGA.W5
PB10B: length 8
  TOP w0.102: BGA.Y5 15.92,12.47 16.14,12.25 16.14,4.76
PB10C: length 12.4
  TOP w0.102: BGA.T7 v1(17.12,16.32)
  L3_SIGNAL w0.102: 17.05,4.75 17.05,14.22 16.73,14.54 16.73,15.93 v1(17.12,16.32)
PB10D: length 11.6
  TOP w0.102: BGA.T8 v1(17.92,15.52)
  L3_SIGNAL w0.102: 17.22,4.75 17.22,14.22 17.53,14.52 17.53,15.13 v1(17.92,15.52)
PB12A: length 8.9
  TOP w0.102: BGA.W6 16.72,13.25 17.11,12.85 17.11,4.76
PB12B: length 8
  TOP w0.102: 16.94,4.76 16.94,12.25 16.72,12.47 BGA.Y6
PB12C: length 13.2
  TOP w0.102: BGA.P9 v1(18.72,17.12)
  BOTTOM w0.102: v1(18.72,17.12) 19.11,16.73 19.11,13.66 18.79,13.34 18.79,4.73
PB12D: length 12.4
  TOP w0.102: BGA.R9 v1(18.72,16.32)
  BOTTOM w0.102: 18.62,4.73 18.62,13.35 18.32,13.65 18.32,15.92 v1(18.72,16.32)
PB13A: length 8.9
  TOP w0.102: BGA.W7 17.52,13.25 17.91,12.85 17.91,4.76
PB13B: length 8
  TOP w0.102: 17.74,4.76 17.74,12.25 17.52,12.47 BGA.Y7
PB13C: length 9.8
  TOP w0.102: BGA.V8 v1(17.92,13.92)
  L3_SIGNAL w0.102: 18.04,4.75 18.04,13.46 17.92,13.58 v1(17.92,13.92)
PB13D: length 10.7
  TOP w0.102: BGA.U9 v1(18.72,14.72)
  L3_SIGNAL w0.102: 18.21,4.75 18.21,13.48 18.32,13.58 18.32,14.32 v1(18.72,14.72)
PB15A: length 8.9
  TOP w0.102: BGA.W8 18.32,13.25 18.71,12.85 18.71,4.76
PB15B: length 8
  TOP w0.102: BGA.Y8 18.32,12.47 18.54,12.25 18.54,4.76
PB15C: length 9.8
  TOP w0.102: BGA.V9 v1(18.72,13.92)
  L3_SIGNAL w0.102: 18.81,4.75 18.81,13.48 18.72,13.57 v1(18.72,13.92)
PB15D: length 11.6
  TOP w0.102: BGA.T9 v1(18.72,15.52)
  L3_SIGNAL w0.102: 18.99,4.75 18.99,13.48 19.12,13.61 19.12,15.12 v1(18.72,15.52)
PB16A: length 8.9
  TOP w0.102: BGA.W9 19.12,13.25 19.51,12.85 19.51,4.76
PB16B: length 8
  TOP w0.102: BGA.Y9 19.12,12.47 19.34,12.25 19.34,4.76
PB16C: length 13.2
  TOP w0.102: BGA.P10 v1(19.52,17.12)
  L4_SIGNAL w0.102: 19.42,4.76 19.42,13.42 19.12,13.71 19.12,16.72 v1(19.52,17.12)
PB16D: length 12.4
  TOP w0.102: BGA.R10 v1(19.52,16.32)
  L4_SIGNAL w0.102: v1(19.52,16.32) 19.92,15.92 19.92,13.74 19.59,13.41 19.59,4.76
PB18A: length 8
  TOP w0.102: BGA.Y10 19.92,12.47 20.14,12.25 20.14,4.76
PB18B: length 8.9
  TOP w0.102: 20.31,4.76 20.31,12.85 19.92,13.25 BGA.W10
PB18C: length 10.7
  TOP w0.102: BGA.U10 v1(19.52,14.72)
  L3_SIGNAL w0.102: 19.82,4.75 19.82,13.42 19.92,13.51 19.92,14.09 19.52,14.49 v1(19.52,14.72)
PB18D: length 9.8
  TOP w0.102: BGA.V10 v1(19.52,13.92)
  L3_SIGNAL w0.102: v1(19.52,13.92) 19.52,13.56 19.65,13.43 19.65,4.75
PB21A: length 8
  TOP w0.102: BGA.Y11 20.72,12.47 20.94,12.25 20.94,4.76
PB21B: length 8.9
  TOP w0.102: BGA.W11 20.72,13.25 21.11,12.85 21.11,4.76
PB21C: length 10.8
  TOP w0.102: BGA.U11 v1(20.32,14.72)
  BOTTOM w0.102: 20.4,4.75 20.4,13.29 20.72,13.61 20.72,14.32 v1(20.32,14.72)
PB21D: length 11.6
  TOP w0.102: BGA.T10 v1(19.52,15.52)
  BOTTOM w0.102: v1(19.52,15.52) 19.92,15.12 19.92,13.6 20.23,13.29 20.23,4.75
PB23A: length 8
  TOP w0.102: BGA.Y12 21.52,12.47 21.74,12.25 21.74,4.76
PB23B: length 8.9
  TOP w0.102: 21.91,4.76 21.91,12.85 21.52,13.25 BGA.W12
PB23C: length 13.9
  TOP w0.102: BGA.P11 v1(20.32,17.12)
  L3_SIGNAL w0.102: 21.28,4.75 21.28,13.35 21.53,13.59 21.53,16.54 21.34,16.73 20.71,16.73 v1(20.32,17.12)
PB23D: length 12.5
  TOP w0.102: BGA.R11 v1(20.32,16.32)
  L3_SIGNAL w0.102: 21.1,4.75 21.1,13.35 20.72,13.73 20.72,15.92 v1(20.32,16.32)
PB26A: length 8
  TOP w0.102: 22.54,4.76 22.54,12.25 22.32,12.47 BGA.Y13
PB26B: length 8.9
  TOP w0.102: 22.71,4.76 22.71,12.85 22.32,13.25 BGA.W13
PB26C: length 10
  TOP w0.102: BGA.V12 v1(21.12,13.92)
  BOTTOM w0.102: v1(21.12,13.92) 21.33,13.92 21.43,13.82 21.43,4.75
PB26D: length 10
  TOP w0.102: BGA.V13 v1(21.92,13.92)
  BOTTOM w0.102: v1(21.92,13.92) 21.71,13.92 21.61,13.82 21.61,4.75
PB28A: length 8
  TOP w0.102: 23.34,4.76 23.34,12.25 23.12,12.47 BGA.Y14
PB28B: length 8.9
  TOP w0.102: 23.51,4.76 23.51,12.85 23.12,13.25 BGA.W14
PB28C: length 10.8
  TOP w0.102: BGA.U12 v1(21.12,14.72)
  L4_SIGNAL w0.102: v1(21.12,14.72) 21.52,14.32 21.52,13.76 21.18,13.42 21.18,4.78
PB28D: length 11.6
  TOP w0.102: BGA.T11 v1(20.32,15.52)
  L4_SIGNAL w0.102: 21,4.78 21,13.42 20.72,13.69 20.72,15.12 v1(20.32,15.52)
PB29A: length 8
  TOP w0.102: BGA.Y15 23.92,12.47 24.14,12.25 24.14,4.76
PB29B: length 8.9
  TOP w0.102: 24.31,4.76 24.31,12.85 23.92,13.25 BGA.W15
PB29C: length 14.2
  TOP w0.102: BGA.P12 v1(21.12,17.12)
  BOTTOM w0.102: v1(21.12,17.12) 21.54,16.7 22.19,16.7 23.11,15.78 23.11,4.72
PB29D: length 13.6
  TOP w0.102: BGA.R12 v1(21.12,16.32)
  BOTTOM w0.102: 22.93,4.72 22.93,15.71 22.72,15.92 21.52,15.92 v1(21.12,16.32)
PB31A: length 8
  TOP w0.102: 24.94,4.76 24.94,12.25 24.72,12.47 BGA.Y16
PB31B: length 8.9
  TOP w0.102: BGA.W16 24.72,13.25 25.11,12.85 25.11,4.76
PB31C: length 12.3
  TOP w0.102: BGA.T12 v1(21.12,15.52)
  BOTTOM w0.102: 22.43,4.72 22.43,14.96 22.28,15.1 21.54,15.1 v1(21.12,15.52)
PB31D: length 11.8
  TOP w0.102: BGA.T13 v1(21.92,15.52)
  BOTTOM w0.102: v1(21.92,15.52) 22.15,15.52 22.6,15.07 22.6,4.72
PB32A: length 8
  TOP w0.102: 25.74,4.76 25.74,12.25 25.52,12.47 BGA.Y17
PB32B: length 8.9
  TOP w0.102: 25.91,4.76 25.91,12.85 25.52,13.25 BGA.W17
PB32C: length 13.4
  TOP w0.102: BGA.P13 v1(21.92,17.12)
  L4_SIGNAL w0.102: v1(21.92,17.12) 21.92,16.91 22.02,16.81 22.27,16.81 22.61,16.47 22.61,4.75
PB32D: length 13.1
  TOP w0.102: BGA.R13 v1(21.92,16.32)
  L4_SIGNAL w0.102: 22.43,4.75 22.43,16.39 22.2,16.63 22.02,16.63 21.92,16.53 v1(21.92,16.32)
PB34A: length 11.3
  TOP w0.102: BGA.V14 v1(23.52,14.72)
  L3_SIGNAL w0.102: v1(23.52,14.72) 23.52,14.93 23.42,15.03 23.32,15.03 23.17,14.88 23.17,4.78
PB34B: length 11.6
  TOP w0.102: BGA.U14 v1(23.52,15.52)
  L3_SIGNAL w0.102: 22.99,4.78 22.99,14.96 23.24,15.21 23.42,15.21 23.52,15.31 v1(23.52,15.52)
PB34C: length 10.8
  TOP w0.102: BGA.V15 v1(24.32,14.72)
  L3_SIGNAL w0.102: 24.63,4.75 24.63,14.62 24.53,14.72 v1(24.32,14.72)
PB34D: length 10.8
  TOP w0.102: BGA.V16 v1(25.12,14.72)
  L3_SIGNAL w0.102: 24.81,4.75 24.81,14.62 24.91,14.72 v1(25.12,14.72)
PB35A: length 8
  TOP w0.102: 26.54,4.76 26.54,12.25 26.32,12.47 BGA.Y18
PB35B: length 8.9
  TOP w0.102: 26.71,4.76 26.71,12.85 26.32,13.25 BGA.W18
PB35C: length 12.9
  TOP w0.102: BGA.T14 v1(23.52,16.32)
  L3_SIGNAL w0.102: v1(23.52,16.32) 23.29,16.32 23.18,16.21 22.86,16.21 22.34,15.69 22.34,4.75
PB35D: length 13.6
  TOP w0.102: BGA.U15 v1(24.32,15.52)
  L3_SIGNAL w0.102: 22.52,4.75 22.52,15.61 22.94,16.03 23.18,16.03 23.29,15.92 23.92,15.92 v1(24.32,15.52)
PB37A: length 8
  TOP w0.102: BGA.Y19 27.12,12.47 27.34,12.25 27.34,4.76
PB37B: length 8.9
  TOP w0.102: BGA.W19 27.12,13.25 27.51,12.85 27.51,4.76
PB37C: length 14.1
  TOP w0.102: BGA.P14 v1(23.52,17.92)
  L4_SIGNAL w0.102: 22.92,4.75 22.92,17.37 23.16,17.61 23.42,17.61 23.52,17.71 v1(23.52,17.92)
PB37D: length 13.8
  TOP w0.102: BGA.R14 v1(23.52,17.12)
  L4_SIGNAL w0.102: 23.1,4.75 23.1,17.3 23.23,17.43 23.42,17.43 23.52,17.33 v1(23.52,17.12)
PB38A: length 8
  TOP w0.102: 28.14,4.76 28.14,12.25 27.92,12.47 BGA.Y20
PB38B: length 8.9
  TOP w0.102: 28.31,4.76 28.31,12.85 27.92,13.25 BGA.W20
PB38C: length 12.5
  TOP w0.102: BGA.T16 v1(25.12,16.32)
  BOTTOM w0.102: 25.2,4.73 25.2,14.03 25.53,14.36 25.53,15.91 v1(25.12,16.32)
PB38D: length 13.2
  TOP w0.102: BGA.R15 v1(24.32,17.12)
  BOTTOM w0.102: 25.03,4.73 25.03,14.03 24.72,14.34 24.72,16.72 v1(24.32,17.12)
PL2A: length 10
  TOP w0.102: BGA.C4 v1(14.72,26.72)
  L3_SIGNAL w0.102: v1(14.72,26.72) 14.51,26.72 14.41,26.82 14.41,35.86
PL2B: length 10
  TOP w0.102: BGA.C3 v1(13.92,26.72)
  L3_SIGNAL w0.102: v1(13.92,26.72) 14.13,26.72 14.23,26.82 14.23,35.86
PL2C: length 12.4
  TOP w0.102: BGA.F6 v1(16.32,24.32)
  BOTTOM w0.102: v1(16.32,24.32) 15.92,24.72 13.64,24.72 13.35,24.43 4.76,24.43
PL2D: length 12.4
  TOP w0.102: BGA.G6 v1(16.32,23.52)
  BOTTOM w0.102: 4.76,24.25 13.35,24.25 13.69,23.92 15.92,23.92 v1(16.32,23.52)
PL3A: length 8.9
  TOP w0.102: BGA.C2 13.25,26.32 12.85,25.93 4.76,25.93
PL3B: length 8
  TOP w0.102: BGA.C1 12.47,26.32 12.25,26.1 4.76,26.1
PL3C: length 10.7
  TOP w0.102: BGA.E4 v1(14.72,25.12)
  L3_SIGNAL w0.102: 4.84,25.39 13.45,25.39 13.57,25.52 14.32,25.52 v1(14.72,25.12)
PL3D: length 9.7
  TOP w0.102: BGA.E3 v1(13.92,25.12)
  L3_SIGNAL w0.102: v1(13.92,25.12) 13.54,25.12 13.45,25.22 4.84,25.22
PL4A: length 8.9
  TOP w0.102: BGA.D2 13.25,25.52 12.85,25.13 4.76,25.13
PL4B: length 8
  TOP w0.102: 4.76,25.3 12.25,25.3 12.47,25.52 BGA.D1
PL4C: length 11.6
  TOP w0.102: BGA.F5 v1(15.52,24.32)
  L4_SIGNAL w0.102: v1(15.52,24.32) 15.12,24.72 13.74,24.72 13.33,24.32 4.78,24.32
PL4D: length 11.6
  TOP w0.102: BGA.G5 v1(15.52,23.52)
  L4_SIGNAL w0.102: v1(15.52,23.52) 15.13,23.91 13.56,23.91 13.33,24.14 4.78,24.14
PL5A: length 10.7
  TOP w0.102: BGA.F4 v1(14.72,24.32)
  L3_SIGNAL w0.102: 4.84,24.59 13.45,24.59 13.57,24.72 14.32,24.72 v1(14.72,24.32)
PL5B: length 9.7
  TOP w0.102: BGA.F3 v1(13.92,24.32)
  L3_SIGNAL w0.102: 4.84,24.41 13.45,24.41 13.54,24.32 v1(13.92,24.32)
PL5C: length 12.4
  TOP w0.102: BGA.H6 v1(16.32,22.72)
  BOTTOM w0.102: 4.76,22.68 13.38,22.68 13.75,22.32 15.92,22.32 v1(16.32,22.72)
PL5D: length 13.2
  TOP w0.102: BGA.H7 v1(17.12,22.72)
  BOTTOM w0.102: v1(17.12,22.72) 16.73,23.11 13.67,23.11 13.42,22.86 4.76,22.86
PL6A: length 8.9
  TOP w0.102: 4.76,24.33 12.85,24.33 13.25,24.72 BGA.E2
PL6B: length 8
  TOP w0.102: BGA.E1 12.47,24.72 12.25,24.5 4.76,24.5
PL6C: length 8.9
  TOP w0.102: BGA.F2 13.25,23.92 12.85,23.53 4.76,23.53
PL6D: length 8
  TOP w0.102: 4.76,23.7 12.25,23.7 12.47,23.92 BGA.F1
PL7A: length 10.7
  TOP w0.102: BGA.G4 v1(14.72,23.52)
  L3_SIGNAL w0.102: 4.84,23.79 13.45,23.79 13.57,23.92 14.32,23.92 v1(14.72,23.52)
PL7B: length 9.7
  TOP w0.102: BGA.G3 v1(13.92,23.52)
  L3_SIGNAL w0.102: 4.84,23.62 13.45,23.62 13.54,23.52 v1(13.92,23.52)
PL7C: length 9.7
  TOP w0.102: BGA.H3 v1(13.92,22.72)
  L3_SIGNAL w0.102: 4.84,22.82 13.45,22.82 13.54,22.72 v1(13.92,22.72)
PL7D: length 10.7
  TOP w0.102: BGA.H4 v1(14.72,22.72)
  L3_SIGNAL w0.102: 4.84,22.99 13.45,22.99 13.56,23.11 14.33,23.11 v1(14.72,22.72)
PL8A: length 8.9
  TOP w0.102: 4.76,22.73 12.85,22.73 13.25,23.12 BGA.G2
PL8B: length 8
  TOP w0.102: BGA.G1 12.47,23.12 12.25,22.9 4.76,22.9
PL8C: length 13
  TOP w0.102: BGA.J6 v1(16.32,21.92)
  L4_SIGNAL w0.102: v1(16.32,21.92) 15.92,22.32 15.92,22.89 15.7,23.11 13.6,23.11 13.38,22.89 4.84,22.89
PL8D: length 11.6
  TOP w0.102: BGA.J5 v1(15.52,21.92)
  L4_SIGNAL w0.102: v1(15.52,21.92) 15.12,22.32 13.76,22.32 13.37,22.71 4.84,22.71
PL9A: length 8.9
  TOP w0.102: 4.76,21.93 12.85,21.93 13.25,22.32 BGA.H2
PL9B: length 8
  TOP w0.102: 4.76,22.1 12.25,22.1 12.47,22.32 BGA.H1
PL9C: length 10.7
  TOP w0.102: BGA.J4 v1(14.72,21.92)
  L3_SIGNAL w0.102: v1(14.72,21.92) 14.32,22.32 13.57,22.32 13.45,22.19 4.84,22.19
PL9D: length 9.7
  TOP w0.102: BGA.J3 v1(13.92,21.92)
  L3_SIGNAL w0.102: 4.84,22.01 13.45,22.01 13.54,21.92 v1(13.92,21.92)
PL10A: length 8.9
  TOP w0.102: BGA.J2 13.25,21.52 12.85,21.13 4.76,21.13
PL10B: length 8
  TOP w0.102: 4.76,21.3 12.25,21.3 12.47,21.52 BGA.J1
PL10C: length 11.5
  TOP w0.102: BGA.K5 v1(15.52,21.12)
  L3_SIGNAL w0.102: 4.84,21.21 13.42,21.21 13.72,21.51 15.13,21.51 v1(15.52,21.12)
PL10D: length 10.7
  TOP w0.102: BGA.K4 v1(14.72,21.12)
  L3_SIGNAL w0.102: 4.84,21.03 13.42,21.03 13.72,20.72 14.32,20.72 v1(14.72,21.12)
PL11A: length 8.9
  TOP w0.102: BGA.K2 13.25,20.72 12.85,20.33 4.76,20.33
PL11B: length 8
  TOP w0.102: BGA.K1 12.47,20.72 12.25,20.5 4.76,20.5
PL11C: length 12.4
  TOP w0.102: BGA.K6 v1(16.32,21.12)
  L4_SIGNAL w0.102: 4.82,21.12 13.35,21.12 13.73,20.73 15.93,20.73 v1(16.32,21.12)
PL11D: length 13.1
  TOP w0.102: BGA.K7 v1(17.12,21.12)
  L4_SIGNAL w0.102: 4.81,21.3 13.36,21.3 13.58,21.51 16.73,21.51 v1(17.12,21.12)
PL12A: length 8
  TOP w0.102: 4.76,19.7 12.25,19.7 12.47,19.92 BGA.L1
PL12B: length 8.9
  TOP w0.102: BGA.L2 13.25,19.92 12.85,19.53 4.76,19.53
PL12C: length 9.7
  TOP w0.102: BGA.L3 v1(13.92,20.32)
  L3_SIGNAL w0.102: 4.84,20.22 13.45,20.22 13.54,20.32 v1(13.92,20.32)
PL12D: length 10.7
  TOP w0.102: BGA.L4 v1(14.72,20.32)
  L3_SIGNAL w0.102: 4.84,20.05 13.45,20.05 13.57,19.92 14.32,19.92 v1(14.72,20.32)
PL15A: length 8
  TOP w0.102: BGA.M1 12.47,19.12 12.25,18.9 4.76,18.9
PL15B: length 8.9
  TOP w0.102: 4.76,18.73 12.85,18.73 13.25,19.12 BGA.M2
PL15C: length 9.7
  TOP w0.102: BGA.M3 v1(13.92,19.52)
  L3_SIGNAL w0.102: v1(13.92,19.52) 13.54,19.52 13.45,19.43 4.84,19.43
PL15D: length 10.7
  TOP w0.102: BGA.M4 v1(14.72,19.52)
  L3_SIGNAL w0.102: 4.84,19.25 13.45,19.25 13.57,19.12 14.32,19.12 v1(14.72,19.52)
PL16A: length 11.5
  TOP w0.102: BGA.L5 v1(15.52,20.32)
  L4_SIGNAL w0.102: v1(15.52,20.32) 15.12,19.92 13.6,19.92 13.37,19.7 4.82,19.7
PL16B: length 11.6
  TOP w0.102: BGA.M5 v1(15.52,19.52)
  L4_SIGNAL w0.102: v1(15.52,19.52) 15.12,19.12 13.79,19.12 13.38,19.52 4.81,19.52
PL16C: length 12.4
  TOP w0.102: BGA.L6 v1(16.32,20.32)
  BOTTOM w0.102: 4.76,20.17 13.45,20.17 13.69,19.92 15.92,19.92 v1(16.32,20.32)
PL16D: length 14
  TOP w0.102: BGA.L7 v1(17.92,20.32)
  BOTTOM w0.102: 4.76,20.34 13.45,20.34 13.83,20.73 16.57,20.73 16.98,20.32 v1(17.92,20.32)
PL17A: length 8
  TOP w0.102: BGA.N1 12.47,18.32 12.25,18.1 4.76,18.1
PL17B: length 8.9
  TOP w0.102: 4.76,17.93 12.85,17.93 13.25,18.32 BGA.N2
PL17C: length 8
  TOP w0.102: 4.76,17.3 12.25,17.3 12.47,17.52 BGA.P1
PL17D: length 8.9
  TOP w0.102: 4.76,17.13 12.85,17.13 13.25,17.52 BGA.P2
PL18A: length 9.7
  TOP w0.102: BGA.N3 v1(13.92,18.72)
  L3_SIGNAL w0.102: v1(13.92,18.72) 13.54,18.72 13.45,18.62 4.84,18.62
PL18B: length 10.7
  TOP w0.102: BGA.N4 v1(14.72,18.72)
  L3_SIGNAL w0.102: 4.84,18.45 13.45,18.45 13.57,18.32 14.32,18.32 v1(14.72,18.72)
PL18C: length 12.4
  TOP w0.102: BGA.M6 v1(16.32,19.52)
  BOTTOM w0.102: v1(16.32,19.52) 15.91,19.11 13.77,19.11 13.39,18.73 4.76,18.73
PL18D: length 14.3
  TOP w0.102: BGA.M7 v1(17.92,19.52)
  BOTTOM w0.102: 4.76,18.56 13.38,18.56 13.62,18.32 16.72,18.32 v1(17.92,19.52)
PL19A: length 9.7
  TOP w0.102: BGA.P3 v1(13.92,17.92)
  L3_SIGNAL w0.102: 4.84,17.82 13.45,17.82 13.54,17.92 v1(13.92,17.92)
PL19B: length 10.7
  TOP w0.102: BGA.P4 v1(14.72,17.92)
  L3_SIGNAL w0.102: 4.84,17.65 13.45,17.65 13.56,17.53 14.33,17.53 v1(14.72,17.92)
PL19C: length 8
  TOP w0.102: BGA.R1 12.47,16.72 12.25,16.5 4.76,16.5
PL19D: length 8.9
  TOP w0.102: BGA.R2 13.25,16.72 12.85,16.33 4.76,16.33
PL21A: length 8
  TOP w0.102: BGA.T1 12.47,15.92 12.25,15.7 4.76,15.7
PL21B: length 8.9
  TOP w0.102: 4.76,15.53 12.85,15.53 13.25,15.92 BGA.T2
PL21C: length 11.5
  TOP w0.102: BGA.N5 v1(15.52,18.72)
  L4_SIGNAL w0.102: 4.84,18.05 13.34,18.05 13.61,18.32 15.12,18.32 v1(15.52,18.72)
PL21D: length 13.1
  TOP w0.102: BGA.N6 v1(16.32,18.72)
  L4_SIGNAL w0.102: 4.84,17.87 13.35,17.87 13.69,17.53 15.77,17.53 15.92,17.68 15.92,18.32 v1(16.32,18.72)
PL22A: length 8
  TOP w0.102: BGA.U1 12.47,15.12 12.25,14.9 4.76,14.9
PL22B: length 8.9
  TOP w0.102: 4.76,14.73 12.85,14.73 13.25,15.12 BGA.U2
PL22C: length 9.7
  TOP w0.102: BGA.R3 v1(13.92,17.12)
  L3_SIGNAL w0.102: 4.84,17.03 13.45,17.03 13.54,17.12 v1(13.92,17.12)
PL22D: length 10.7
  TOP w0.102: BGA.R4 v1(14.72,17.12)
  L3_SIGNAL w0.102: v1(14.72,17.12) 14.32,16.72 13.57,16.72 13.45,16.85 4.84,16.85
PL23A: length 9.7
  TOP w0.102: BGA.T3 v1(13.92,16.32)
  L3_SIGNAL w0.102: 4.84,16.22 13.45,16.22 13.54,16.32 v1(13.92,16.32)
PL23B: length 10.7
  TOP w0.102: BGA.T4 v1(14.72,16.32)
  L3_SIGNAL w0.102: v1(14.72,16.32) 14.32,15.92 13.57,15.92 13.45,16.05 4.84,16.05
PL23C: length 8
  TOP w0.102: 4.76,14.1 12.25,14.1 12.47,14.32 BGA.V1
PL23D: length 8.9
  TOP w0.102: 4.76,13.93 12.85,13.93 13.25,14.32 BGA.V2
PL24A: length 10.8
  TOP w0.102: BGA.V3 v1(13.92,14.72)
  L3_SIGNAL w0.102: v1(13.92,14.72) 14.13,14.72 14.23,14.62 14.23,4.78
PL24B: length 10.8
  TOP w0.102: BGA.V4 v1(14.72,14.72)
  L3_SIGNAL w0.102: v1(14.72,14.72) 14.51,14.72 14.41,14.62 14.41,4.78
PL24C: length 14
  TOP w0.102: BGA.P5 v1(15.52,17.92)
  BOTTOM w0.102: 15.47,4.75 15.47,14.16 15.13,14.5 15.13,17.53 v1(15.52,17.92)
PL24D: length 14
  TOP w0.102: BGA.P6 v1(16.32,17.92)
  BOTTOM w0.102: v1(16.32,17.92) 15.92,17.52 15.92,14.43 15.64,14.16 15.64,4.75
PL25A: length 11.5
  TOP w0.102: BGA.T5 v1(15.52,16.32)
  L4_SIGNAL w0.102: v1(15.52,16.32) 15.12,15.92 13.57,15.92 13.35,16.14 4.84,16.14
PL25B: length 11.6
  TOP w0.102: BGA.R5 v1(15.52,17.12)
  L4_SIGNAL w0.102: 4.84,16.32 13.34,16.32 13.75,16.73 15.13,16.73 v1(15.52,17.12)
PL25C: length 11.6
  TOP w0.102: BGA.U4 v1(14.72,15.52)
  L4_SIGNAL w0.102: 14.66,4.78 14.66,14.22 14.32,14.56 14.32,15.12 v1(14.72,15.52)
PL25D: length 11.6
  TOP w0.102: BGA.U5 v1(15.52,15.52)
  L4_SIGNAL w0.102: 14.84,4.78 14.84,14.22 15.12,14.5 15.12,15.12 v1(15.52,15.52)
PR2A: length 10.9
  TOP w0.102: BGA.D17 v1(25.92,25.92)
  L4_SIGNAL w0.102: 25.96,35.89 25.96,27.38 26.33,27.01 26.33,26.33 v1(25.92,25.92)
PR2B: length 10
  TOP w0.102: BGA.C18 v1(26.72,26.72)
  L4_SIGNAL w0.102: 26.13,35.89 26.13,27.45 26.52,27.07 26.52,26.92 v1(26.72,26.72)
PR2C: length 12.4
  TOP w0.102: BGA.F15 v1(24.32,24.32)
  BOTTOM w0.102: 35.86,24.43 28.09,24.43 27.8,24.72 24.72,24.72 v1(24.32,24.32)
PR2D: length 12.4
  TOP w0.102: BGA.G15 v1(24.32,23.52)
  BOTTOM w0.102: v1(24.32,23.52) 24.71,23.91 27.75,23.91 28.09,24.25 35.86,24.25
PR3A: length 9
  TOP w0.102: BGA.C19 v1(27.52,26.72)
  L3_SIGNAL w0.102: v1(27.52,26.72) 27.7,26.72 27.91,26.51 35.86,26.51
PR3B: length 11.3
  TOP w0.102: BGA.E17 v1(25.92,25.12)
  L3_SIGNAL w0.102: v1(25.92,25.12) 26.33,25.53 26.33,26.08 26.58,26.33 35.86,26.33
PR3C: length 11.7
  TOP w0.102: BGA.F16 v1(25.12,24.32)
  L4_SIGNAL w0.102: 35.89,25.1 27.34,25.1 26.97,24.72 25.52,24.72 v1(25.12,24.32)
PR3D: length 10
  TOP w0.102: BGA.D18 v1(26.72,25.92)
  L4_SIGNAL w0.102: v1(26.72,25.92) 27.37,25.27 35.89,25.27
PR4A: length 8.1
  TOP w0.102: BGA.B20 28.23,26.81 35.88,26.81
PR4B: length 8.1
  TOP w0.102: BGA.C20 28.23,26.63 35.88,26.63
PR4C: length 14
  TOP w0.102: BGA.H14 v1(22.72,22.72)
  L4_SIGNAL w0.102: v1(22.72,22.72) 23.11,23.11 28.52,23.11 28.84,22.79 35.89,22.79
PR4D: length 13.2
  TOP w0.102: BGA.H15 v1(23.52,22.72)
  L4_SIGNAL w0.102: 35.89,22.61 28.83,22.61 28.54,22.32 23.92,22.32 v1(23.52,22.72)
PR5A: length 9.2
  TOP w0.102: BGA.D19 v1(27.52,25.92)
  L3_SIGNAL w0.102: 35.89,25.37 28.07,25.37 v1(27.52,25.92)
PR5B: length 10.9
  TOP w0.102: BGA.F17 v1(25.92,24.32)
  L3_SIGNAL w0.102: v1(25.92,24.32) 26.32,24.72 27.59,24.72 28.06,25.19 35.89,25.19
PR5C: length 8
  TOP w0.102: 35.86,25.3 28.42,25.3 28.2,25.52 BGA.D20
PR5D: length 8.9
  TOP w0.102: 35.88,25.12 27.52,25.12 BGA.E19
PR6A: length 11.6
  TOP w0.102: BGA.G16 v1(25.12,23.52)
  L4_SIGNAL w0.102: 35.88,23.56 27.35,23.56 27.01,23.91 25.51,23.91 v1(25.12,23.52)
PR6B: length 10
  TOP w0.102: BGA.F18 v1(26.72,24.32)
  L4_SIGNAL w0.102: 35.88,23.74 27.43,23.74 27.07,24.1 26.94,24.1 v1(26.72,24.32)
PR6C: length 10.7
  TOP w0.102: BGA.G17 v1(25.92,23.52)
  L3_SIGNAL w0.102: v1(25.92,23.52) 26.31,23.91 35.86,23.91
PR6D: length 9
  TOP w0.102: BGA.E20 v1(27.52,24.32)
  L3_SIGNAL w0.102: 35.86,24.1 28.06,24.1 27.84,24.32 v1(27.52,24.32)
PR7A: length 8.9
  TOP w0.102: BGA.F19 27.41,23.92 27.81,23.52 35.88,23.52
PR7B: length 8
  TOP w0.102: 35.88,23.69 28.41,23.69 28.19,23.92 BGA.F20
PR7C: length 13.2
  TOP w0.102: BGA.J14 v1(23.52,21.92)
  BOTTOM w0.102: v1(23.52,21.92) 23.92,22.32 25.34,22.32 25.65,22.01 35.89,22.01
PR7D: length 12.4
  TOP w0.102: BGA.J15 v1(24.32,21.92)
  BOTTOM w0.102: 35.89,21.84 25.63,21.84 25.31,21.51 24.73,21.51 v1(24.32,21.92)
PR8A: length 9.3
  TOP w0.102: BGA.G19 v1(27.52,22.72)
  BOTTOM w0.102: 35.89,23.24 27.87,23.24 27.66,23.02 27.66,22.86 v1(27.52,22.72)
PR8B: length 11.6
  TOP w0.102: BGA.H17 v1(25.12,22.72)
  BOTTOM w0.102: v1(25.12,22.72) 25.51,23.11 27.49,23.11 27.8,23.42 35.89,23.42
PR8C: length 12.4
  TOP w0.102: BGA.H16 v1(24.32,22.72)
  L3_SIGNAL w0.102: v1(24.32,22.72) 24.71,23.11 28.67,23.11 28.88,22.9 35.86,22.9
PR8D: length 8.1
  TOP w0.102: BGA.G20 v1(28.32,22.72)
  L3_SIGNAL w0.102: 35.86,22.72 v1(28.32,22.72)
PR9A: length 11
  TOP w0.102: BGA.H18 v1(25.92,22.72)
  L3_SIGNAL w0.102: v1(25.92,22.72) 26.13,22.72 26.23,22.62 26.23,22.3 26.5,22.03 35.86,22.03
PR9B: length 10.7
  TOP w0.102: BGA.H19 v1(26.72,22.72)
  L3_SIGNAL w0.102: v1(26.72,22.72) 26.51,22.72 26.41,22.62 26.41,22.37 26.57,22.21 35.86,22.21
PR9C: length 10.5
  TOP w0.102: BGA.J17 25.91,21.91 35.88,21.91
PR9D: length 8.1
  TOP w0.102: BGA.H20 27.93,22.32 28.16,22.09 35.88,22.09
PR10A: length 9.7
  TOP w0.102: BGA.J18 v1(26.72,21.12)
  L3_SIGNAL w0.102: v1(26.72,21.12) 27.09,21.12 27.19,21.23 35.85,21.23
PR10B: length 11.5
  TOP w0.102: BGA.J16 v1(25.12,21.92)
  L3_SIGNAL w0.102: 35.86,21.4 27.19,21.4 27.09,21.51 25.53,21.51 v1(25.12,21.92)
PR10C: length 13.2
  TOP w0.102: BGA.K14 v1(23.52,21.12)
  L4_SIGNAL w0.102: 35.89,21.31 27.26,21.31 27.05,21.51 23.91,21.51 v1(23.52,21.12)
PR10D: length 12.5
  TOP w0.102: BGA.K15 v1(24.32,21.12)
  L4_SIGNAL w0.102: v1(24.32,21.12) 24.72,20.72 26.85,20.72 27.26,21.13 35.88,21.13
PR11A: length 8.9
  TOP w0.102: BGA.J19 27.39,21.52 27.79,21.13 35.88,21.13
PR11B: length 8
  TOP w0.102: 35.88,21.3 28.39,21.3 28.17,21.52 BGA.J20
PR11C: length 10.7
  TOP w0.102: BGA.K17 v1(25.92,21.12)
  L3_SIGNAL w0.102: 35.86,20.6 27.1,20.6 26.98,20.72 26.32,20.72 v1(25.92,21.12)
PR11D: length 9.8
  TOP w0.102: BGA.K18 v1(26.72,20.32)
  L3_SIGNAL w0.102: 35.86,20.42 27.1,20.42 27,20.32 v1(26.72,20.32)
PR12A: length 8.9
  TOP w0.102: BGA.K19 27.39,20.72 27.79,20.33 35.88,20.33
PR12B: length 8
  TOP w0.102: 35.88,20.5 28.39,20.5 28.17,20.72 BGA.K20
PR12C: length 11.6
  TOP w0.102: BGA.K16 v1(25.12,21.12)
  BOTTOM w0.102: 35.89,21.19 27.32,21.19 26.99,21.51 25.79,21.51 25.39,21.12 v1(25.12,21.12)
PR12D: length 10.8
  TOP w0.102: BGA.L17 v1(25.92,20.32)
  BOTTOM w0.102: 35.89,21.01 27.3,21.01 27.01,20.72 26.32,20.72 v1(25.92,20.32)
PR15A: length 8.9
  TOP w0.102: BGA.L19 27.39,19.92 27.79,19.53 35.88,19.53
PR15B: length 8
  TOP w0.102: 35.88,19.7 28.39,19.7 28.17,19.92 BGA.L20
PR15C: length 13.9
  TOP w0.102: BGA.L14 v1(23.52,20.32)
  BOTTOM w0.102: v1(23.52,20.32) 23.91,19.93 23.91,19.27 24.07,19.11 26.98,19.11 27.29,19.42 35.88,19.42
PR15D: length 12.4
  TOP w0.102: BGA.L15 v1(24.32,20.32)
  BOTTOM w0.102: v1(24.32,20.32) 24.72,19.92 26.98,19.92 27.29,19.61 35.88,19.61
PR16A: length 8
  TOP w0.102: BGA.M20 28.17,19.12 28.39,18.9 35.88,18.9
PR16B: length 8.9
  TOP w0.102: BGA.M19 27.39,19.12 27.79,18.73 35.88,18.73
PR16C: length 11.7
  TOP w0.102: BGA.L16 v1(25.12,20.32)
  L3_SIGNAL w0.102: 35.89,19.57 27.38,19.57 27.03,19.92 25.52,19.92 v1(25.12,20.32)
PR16D: length 10
  TOP w0.102: BGA.M18 v1(26.72,18.72)
  L3_SIGNAL w0.102: 35.89,19.39 27.39,19.39 v1(26.72,18.72)
PR17A: length 11.4
  TOP w0.102: BGA.M17 v1(25.92,19.52)
  L3_SIGNAL w0.102: v1(25.92,19.52) 26.33,19.11 26.33,18.49 26.5,18.32 28.48,18.32 28.6,18.2 35.86,18.2
PR17B: length 8.2
  TOP w0.102: BGA.N20 v1(28.32,17.92)
  L3_SIGNAL w0.102: v1(28.32,17.92) 28.49,17.92 28.6,18.02 35.86,18.02
PR17C: length 12.8
  TOP w0.102: BGA.M16 v1(25.12,19.52)
  L3_SIGNAL w0.102: 35.85,17.2 27.65,17.2 27.33,17.52 26.59,17.52 26.33,17.78 26.33,18.09 26.1,18.32 25.66,18.32 25.52,18.46 25.52,19.12 v1(25.12,19.52)
PR17D: length 9.3
  TOP w0.102: BGA.N19 v1(27.52,17.92)
  L3_SIGNAL w0.102: v1(27.52,17.92) 27.52,17.58 27.72,17.38 35.86,17.38
PR18A: length 10
  TOP w0.102: BGA.N18 v1(26.72,17.92)
  L4_SIGNAL w0.102: v1(26.72,17.92) 26.94,18.14 27.03,18.14 27.42,18.53 35.86,18.53
PR18B: length 10.8
  TOP w0.102: BGA.N17 v1(25.92,18.72)
  L4_SIGNAL w0.102: 35.86,18.71 27.35,18.71 26.96,18.32 26.32,18.32 v1(25.92,18.72)
PR18C: length 8
  TOP w0.102: BGA.P20 28.17,17.52 28.39,17.3 35.88,17.3
PR18D: length 8.9
  TOP w0.102: 35.88,17.13 27.79,17.13 27.39,17.52 BGA.P19
PR19A: length 9.9
  TOP w0.102: BGA.P18 v1(26.72,17.12)
  L3_SIGNAL w0.102: v1(26.72,17.12) 27.14,16.7 28.59,16.7 28.68,16.6 35.86,16.6
